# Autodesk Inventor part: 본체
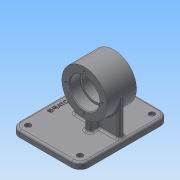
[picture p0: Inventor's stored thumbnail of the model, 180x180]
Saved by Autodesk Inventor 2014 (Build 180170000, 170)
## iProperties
Created: 2019-09
Part Number: 본체
Material: 일반
Document SubType Name: Modeling
Designer: net
Density: 1 g/cm^3
Appearance: 기본값
Author: net
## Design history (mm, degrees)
sketch "스케치1"
  geometry: L1 (-21, 32)-(21, 32); L2 (21, 32)-(21, 0); L3 (21, 0)-(-21, 0); L4 (-21, 0)-(-21, 32); L5 (-21, 0)-(-6, 0); L6 (-6, 0)-(-6, 21); L7 (-6, 21)-(-21, 21); L8 (-21, 21)-(-21, 0); L9 (-6, 0)-(6, 0); L10 (6, 0)-(6, 18); L11 (6, 18)-(-6, 18); L12 (-6, 18)-(-6, 0); L13 (6, 0)-(21, 0); L14 (21, 0)-(21, 21); L15 (21, 21)-(6, 21); L16 (6, 21)-(6, 0); 2 further points
  constraints: 32 end point, 8 parallel, 4 horizontal, 4 perpendicular, 2 midpoint, 1 coincident, 1 point on line
  dimensions: "d0" = 42 distance between parallel lines of L2 L4; "d1" = 15 distance of L6.end L7.end; "d2" = 15 distance of L14.end L15.end (= d1); "d3" = 64 diameter of L1 L13; "d4" = 42 diameter of L15 L3; "d5" = 42 diameter of L7 L5; "d6" = 36 diameter of L11 L3
revolve "회전1" sketch "스케치1" stored, may be unused: angle "d7" = 90 deg
sketch "스케치2" dims "d8" = 52
  geometry: C1 r 21 at (0, 0) reference; C2 r 32 at (0, 0) reference; 2 further points
  constraints: 2 vertical alignment, 1 coincident, 2 other
hole "구멍1" sketch "스케치2" at (0, 26) diameter "d9" = 3.242; stored, may be unused: countersink angle "d13" = 90 deg, drill point angle "d15" = 118 deg; dims "d10" = 8, "d11" = 4, "d12" = 2, "d14" = 10
chamfer "모따기1" distance "d19" = 1; stored, may be unused: second distance "d20" = 2, angle "d21" = 45 deg
fillet "모깎기1" dims "d22" = 0.3
node "작업 평면1"
sketch "스케치4"
  geometry: L1 (-4, -17)-(4, -17); L2 (4, -17)-(4, 17); L3 (4, 17)-(-4, 17); L4 (-4, 17)-(-4, -17); L5 (-4, -17)-(4, 17); L6 (4, -17)-(-4, 17); L7 (-32, -4)-(32, -4); L8 (32, -4)-(32, 4); L9 (32, 4)-(-32, 4); L10 (-32, 4)-(-32, -4); L11 (-32, -4)-(32, 4); L12 (32, -4)-(-32, 4); 1 further point
  constraints: 24 end point, 4 midpoint, 4 parallel, 2 horizontal, 2 perpendicular
  dimensions: "d26" = 8 distance of L2.end L3.end; "d27" = 8 distance of L9.end L7.start; "d28" = 64 distance of L8.end L9.end; "d29" = 34 distance of L3.end L1.start
extrude "돌출1" join sketch "스케치4" stored distance "d30" = 10; taper "d31" = 0 deg
sketch "스케치5"
  geometry: L1 (-62, -63)-(36, -63); L2 (36, -63)-(36, 63); L3 (36, 63)-(-62, 63); L4 (-62, 63)-(-62, -63); L5 (-62, -63)-(36, 63); L6 (36, -63)-(-62, 63); 3 further points
  constraints: 12 end point, 3 midpoint, 2 parallel, 1 horizontal, 1 horizontal alignment, 1 perpendicular
  dimensions: "d32" = 98 distance of L2.end L3.end; "d33" = 126 distance of L3.end L1.start; "d34" = 62 distance from line of L4 point (0, 0)
extrude "돌출2" join sketch "스케치5" distance "d35" = 9; taper "d36" = 0 deg
fillet "모깎기2" dims "d37" = 12
sketch "스케치6"
  geometry: A1 r 12 centre (-50, 51) between (-50, 63) and (-62, 51) reference; A2 r 12 centre (-50, -51) between (-62, -51) and (-50, -63) reference; A3 r 12 centre (24, -51) between (24, -63) and (36, -51) reference; A4 r 12 centre (24, 51) between (36, 51) and (24, 63) reference; 1 further point
hole "구멍2" sketch "스케치6" at (24, -51), (-50, -51), (24, 51), (-50, 51) diameter "d40" = 4.5; stored, may be unused: countersink angle "d44" = 90 deg, drill point angle "d46" = 118 deg; dims "d41" = 8, "d42" = 8, "d43" = 4.4, "d45" = 10
fillet "모깎기5" dims "d47" = 3
sketch "스케치7"
  geometry: L1 (-62, 51)-(-62, -51) reference; L2 (24, 63)-(-50, 63) reference; 2 further points
  constraints: 1 other
  dimensions: "d48" = 10 distance from line of L1 point (-52, 0); "d49" = 63 distance from line of L2 point (-52, 0)
feature "엠보싱1" sketch "스케치7" dims "d0" = 42, "d1" = 15, "d2" = 15 (= d1), "d3" = 64, "d4" = 42, "d5" = 42, "d6" = 36, "d8" = 52, "d50" = 0.5, "d51" = 0
fillet "모깎기6" dims "d52" = 3
fillet "모깎기7" dims "d53" = 3
node "솔리드1"
pattern_circular "원형 패턴1" dims angle "d17" = 360 deg
mirror "대칭1"
other parameters: "d23" = -59
